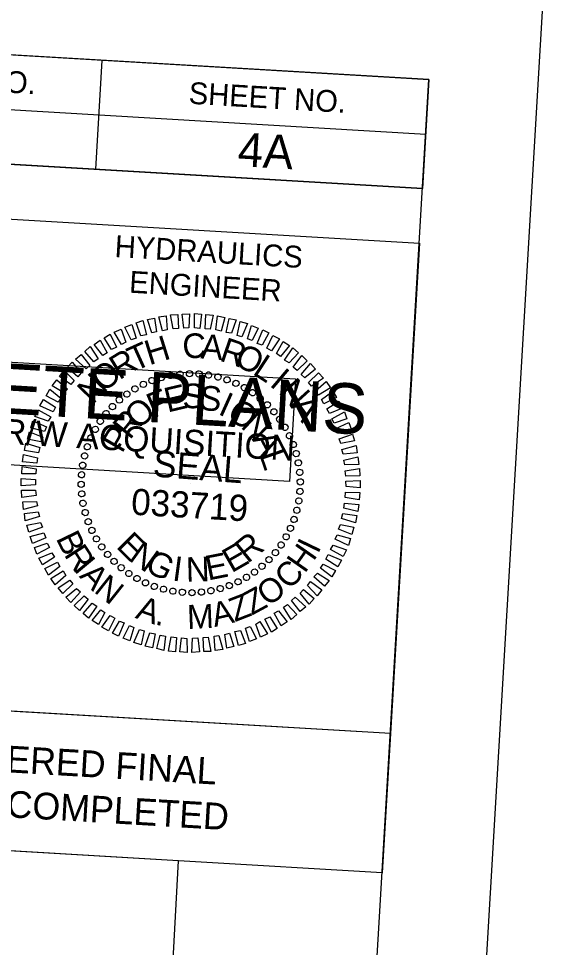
# Model space of a CAD drawing. Extents: x 2010810 to 2012732, y 444258 to 445456.
# Drawn here: x 2012611.9 to 2012732.3, y 445134 to 445346.8 of the extents above; entities that cross this region are included whole.
import ezdxf

# ---------------------------------------------------------------- set-up
doc = ezdxf.new("R2010")
doc.units = 0
for name, color, linetype in [('Sheet Clip Boundary CELL', 7, 'Continuous'), ('Sheet Data Field CELL', 7, 'Continuous'), ('Sheet Plan And Profile CELL', 7, 'Continuous'), ('Sheet Plot Border Outside CELL', 7, 'Continuous'), ('Sheet Professional Seal CELL', 7, 'Continuous'), ('Sheet Profile Grid Minor CELL', 7, 'Continuous'), ('Sheet Sticker Exception Certification CELL', 7, 'Continuous'), ('Sheet Sticker Incomplete CELL', 7, 'Continuous')]:
    doc.layers.add(name, color=color, linetype=linetype)

msp = doc.modelspace()

# ---------------------------------------------------------------- linework, layer by layer
at = {"layer": 'Sheet Clip Boundary CELL'}
msp.add_lwpolyline([(2011147.85, 444375), (2012145.7, 444317.47), (2012151.4, 444414.1), (2011981.99, 444424.08), (2012065.05, 444531.98), (2012116.09, 444528.98), (2012447, 444433.71), (2012447.13, 444434.15), (2012512.37, 444430.3), (2012650.61, 444422.16), (2012668.12, 444720.33), (2012623.18, 444722.98), (2012629.52, 444823.68), (2012643.65, 445063.27), (2012648.58, 445153.9), (2012495.5, 445162.92), (2012502.28, 445278.05), (2012302.58, 445289.82), (2012278.52, 445262.33), (2012176.97, 445268.45), (2011765.99, 445293.2), (2011771.61, 445387.92), (2011477.93, 445405.24)], dxfattribs=at)
at = {"layer": 'Sheet Plan And Profile CELL'}
for p, q in [((2012631.04, 445337.21), (2012629.57, 445312.26)), ((2012505.47, 445332.09), (2012705.17, 445320.32)), ((2012504.73, 445319.61), (2012704.44, 445307.84))]:
    msp.add_line(p, q, dxfattribs=at)
for points in [[(2012705.91, 445332.85), (2011208.51, 445421.12), (2011146.72, 444372.94), (2012644.12, 444284.67)], [(2012506.21, 445344.62), (2012705.91, 445332.85), (2012704.44, 445307.84), (2012504.73, 445319.61)], [(2012603.87, 445301.25), (2012703.7, 445295.36), (2012697.08, 445183.06), (2012597.25, 445188.94)]]:
    msp.add_lwpolyline(points, close=True, dxfattribs=at)
at = {"layer": 'Sheet Plot Border Outside CELL'}
msp.add_lwpolyline([(2010970.55, 444358.28), (2012667.61, 444258.24), (2012732.34, 445356.33), (2011035.28, 445456.37)], close=True, dxfattribs=at)
at = {"layer": 'Sheet Professional Seal CELL'}
for p, q in [((2012646.7, 445265.05), (2012646.7, 445265.05)), ((2012648.92, 445265.32), (2012648.92, 445265.32)), ((2012651.08, 445265.49), (2012651.08, 445265.49)), ((2012653.28, 445265.41), (2012653.28, 445265.41)), ((2012655.47, 445265.13), (2012655.47, 445265.13)), ((2012640.52, 445263.01), (2012640.52, 445263.01)), ((2012642.52, 445263.89), (2012642.52, 445263.89)), ((2012644.56, 445264.57), (2012644.56, 445264.57)), ((2012657.59, 445264.66), (2012657.59, 445264.66)), ((2012659.66, 445264.09), (2012659.66, 445264.09)), ((2012661.72, 445263.26), (2012661.72, 445263.26)), ((2012636.73, 445260.83), (2012636.73, 445260.83)), ((2012638.55, 445261.97), (2012638.55, 445261.97)), ((2012663.66, 445262.25), (2012663.66, 445262.25)), ((2012665.55, 445261.13), (2012665.55, 445261.13)), ((2012634.99, 445259.43), (2012634.99, 445259.43)), ((2012667.27, 445259.78), (2012667.27, 445259.78)), ((2012633.41, 445257.97), (2012633.41, 445257.97)), ((2012668.94, 445258.33), (2012668.94, 445258.33)), ((2012670.4, 445256.74), (2012670.4, 445256.74)), ((2012630.6, 445254.58), (2012630.6, 445254.58)), ((2012631.96, 445256.3), (2012631.96, 445256.3)), ((2012671.8, 445255.01), (2012671.8, 445255.01)), ((2012629.49, 445252.69), (2012629.49, 445252.69)), ((2012672.94, 445253.18), (2012672.94, 445253.18)), ((2012628.47, 445250.75), (2012628.47, 445250.75)), ((2012673.98, 445251.22), (2012673.98, 445251.22)), ((2012627.65, 445248.69), (2012627.65, 445248.69)), ((2012674.86, 445249.22), (2012674.86, 445249.22)), ((2012627.08, 445246.62), (2012627.08, 445246.62)), ((2012675.54, 445247.17), (2012675.54, 445247.17)), ((2012626.6, 445244.5), (2012626.6, 445244.5)), ((2012676.02, 445245.04), (2012676.02, 445245.04)), ((2012626.32, 445242.31), (2012626.32, 445242.31)), ((2012676.29, 445242.82), (2012676.29, 445242.82)), ((2012626.24, 445240.11), (2012626.24, 445240.11)), ((2012651.35, 445240.38), (2012651.35, 445240.38)), ((2012676.46, 445240.66), (2012676.46, 445240.66)), ((2012626.42, 445237.95), (2012626.42, 445237.95)), ((2012676.38, 445238.46), (2012676.38, 445238.46)), ((2012626.69, 445235.73), (2012626.69, 445235.73)), ((2012676.1, 445236.27), (2012676.1, 445236.27)), ((2012627.16, 445233.6), (2012627.16, 445233.6)), ((2012675.63, 445234.14), (2012675.63, 445234.14)), ((2012627.84, 445231.55), (2012627.84, 445231.55)), ((2012675.05, 445232.07), (2012675.05, 445232.07)), ((2012628.73, 445229.55), (2012628.73, 445229.55)), ((2012674.23, 445230.02), (2012674.23, 445230.02)), ((2012629.76, 445227.58), (2012629.76, 445227.58)), ((2012673.22, 445228.08), (2012673.22, 445228.08)), ((2012630.91, 445225.76), (2012630.91, 445225.76)), ((2012670.75, 445224.46), (2012670.75, 445224.46)), ((2012672.1, 445226.19), (2012672.1, 445226.19)), ((2012632.31, 445224.03), (2012632.31, 445224.03)), ((2012633.77, 445222.44), (2012633.77, 445222.44)), ((2012669.3, 445222.8), (2012669.3, 445222.8)), ((2012635.43, 445220.99), (2012635.43, 445220.99)), ((2012667.71, 445221.34), (2012667.71, 445221.34)), ((2012637.16, 445219.63), (2012637.16, 445219.63)), ((2012639.04, 445218.52), (2012639.04, 445218.52)), ((2012664.15, 445218.79), (2012664.15, 445218.79)), ((2012665.97, 445219.94), (2012665.97, 445219.94)), ((2012640.99, 445217.5), (2012640.99, 445217.5)), ((2012643.04, 445216.68), (2012643.04, 445216.68)), ((2012645.11, 445216.11), (2012645.11, 445216.11)), ((2012658.14, 445216.19), (2012658.14, 445216.19)), ((2012660.18, 445216.87), (2012660.18, 445216.87)), ((2012662.19, 445217.76), (2012662.19, 445217.76)), ((2012647.24, 445215.63), (2012647.24, 445215.63)), ((2012649.43, 445215.35), (2012649.43, 445215.35)), ((2012651.63, 445215.27), (2012651.63, 445215.27)), ((2012653.79, 445215.45), (2012653.79, 445215.45)), ((2012656.01, 445215.72), (2012656.01, 445215.72))]:
    msp.add_line(p, q, dxfattribs=at)
for points in [[(2012642.46, 445274.77), (2012641.49, 445277.83), (2012643.06, 445278.19), (2012643.53, 445275.05)], [(2012644.89, 445275.27), (2012644.03, 445278.48), (2012645.75, 445278.73), (2012645.96, 445275.46)], [(2012647.32, 445275.68), (2012646.71, 445278.92), (2012648.37, 445278.98), (2012648.53, 445275.76)], [(2012649.74, 445275.84), (2012649.38, 445279.07), (2012651.08, 445279.17), (2012650.94, 445275.92)], [(2012652.25, 445275.94), (2012652.19, 445279.2), (2012653.83, 445279.05), (2012653.44, 445275.82)], [(2012654.64, 445275.75), (2012654.83, 445279), (2012656.47, 445278.85), (2012655.83, 445275.63)], [(2012657.13, 445275.45), (2012657.52, 445278.69), (2012659.15, 445278.29), (2012658.31, 445275.18)], [(2012659.5, 445274.91), (2012660.14, 445278.08), (2012661.77, 445277.74), (2012660.69, 445274.69)], [(2012635.49, 445272.12), (2012633.8, 445274.93), (2012635.4, 445275.63), (2012636.48, 445272.66)], [(2012637.71, 445273.19), (2012636.28, 445276.08), (2012637.87, 445276.69), (2012638.83, 445273.58)], [(2012639.97, 445274.11), (2012638.84, 445277.08), (2012640.37, 445277.59), (2012641.23, 445274.34)], [(2012662.01, 445274.21), (2012662.7, 445277.43), (2012664.38, 445276.93), (2012663.05, 445273.9)], [(2012664.37, 445273.42), (2012665.3, 445276.48), (2012666.82, 445275.88), (2012665.4, 445273.01)], [(2012633.22, 445271), (2012631.53, 445273.66), (2012632.88, 445274.53), (2012634.36, 445271.54)], [(2012666.56, 445272.39), (2012667.9, 445275.47), (2012669.26, 445274.79), (2012667.69, 445271.98)], [(2012668.75, 445271.31), (2012670.17, 445274.18), (2012671.68, 445273.39), (2012669.82, 445270.7)], [(2012629.15, 445268.19), (2012627.08, 445270.51), (2012628.35, 445271.64), (2012630.14, 445268.83)], [(2012631.24, 445269.62), (2012629.23, 445272.14), (2012630.64, 445273.11), (2012632.22, 445270.21)], [(2012670.98, 445270.03), (2012672.5, 445272.8), (2012673.94, 445271.86), (2012671.89, 445269.37)], [(2012672.85, 445268.57), (2012674.77, 445271.36), (2012676, 445270.23), (2012673.91, 445267.9)], [(2012627.4, 445266.54), (2012624.98, 445268.73), (2012626.29, 445269.81), (2012628.25, 445267.29)], [(2012674.81, 445266.95), (2012676.81, 445269.59), (2012678.05, 445268.41), (2012675.71, 445266.19)], [(2012625.54, 445264.74), (2012623.06, 445266.84), (2012624.24, 445268.08), (2012626.29, 445265.6)], [(2012676.61, 445265.29), (2012678.81, 445267.76), (2012679.94, 445266.5), (2012677.52, 445264.49)], [(2012623.93, 445262.94), (2012621.34, 445264.79), (2012622.37, 445266.18), (2012624.64, 445263.85)], [(2012678.31, 445263.44), (2012680.59, 445265.66), (2012681.72, 445264.39), (2012679.01, 445262.59)], [(2012622.32, 445261.03), (2012619.61, 445262.69), (2012620.69, 445264.03), (2012623.17, 445261.88)], [(2012679.95, 445261.54), (2012682.38, 445263.65), (2012683.34, 445262.24), (2012680.59, 445260.5)], [(2012620.99, 445258.95), (2012618.22, 445260.37), (2012619.06, 445261.87), (2012621.65, 445259.87)], [(2012681.33, 445259.5), (2012683.9, 445261.45), (2012684.76, 445259.95), (2012681.87, 445258.52)], [(2012619.86, 445256.71), (2012616.83, 445258.05), (2012617.67, 445259.55), (2012620.42, 445257.78)], [(2012682.51, 445257.38), (2012685.26, 445259.12), (2012686.12, 445257.57), (2012683.15, 445256.34)], [(2012618.73, 445254.58), (2012615.69, 445255.66), (2012616.43, 445257.17), (2012619.34, 445255.59)], [(2012683.67, 445255.11), (2012686.57, 445256.69), (2012687.13, 445255.1), (2012684.22, 445254.12)], [(2012617.84, 445252.23), (2012614.78, 445253.06), (2012615.23, 445254.68), (2012618.3, 445253.25)], [(2012684.55, 445252.9), (2012687.58, 445254.23), (2012688.13, 445252.59), (2012684.98, 445251.77)], [(2012617.05, 445249.87), (2012613.98, 445250.45), (2012614.43, 445252.13), (2012617.51, 445250.89)], [(2012685.31, 445250.5), (2012688.43, 445251.62), (2012688.89, 445250.04), (2012685.74, 445249.43)], [(2012616.5, 445247.35), (2012613.32, 445247.83), (2012613.62, 445249.52), (2012616.82, 445248.53)], [(2012685.96, 445248.06), (2012689.23, 445249.02), (2012689.43, 445247.35), (2012686.25, 445246.99)], [(2012616.11, 445244.97), (2012612.87, 445245.26), (2012613.07, 445246.9), (2012616.28, 445246.16)], [(2012686.42, 445245.63), (2012689.62, 445246.39), (2012689.82, 445244.68), (2012686.66, 445244.56)], [(2012615.91, 445242.47), (2012612.66, 445242.51), (2012612.76, 445244.21), (2012615.98, 445243.67)], [(2012686.73, 445243.21), (2012690.02, 445243.71), (2012690.07, 445242.01), (2012686.86, 445242)], [(2012615.82, 445239.97), (2012612.55, 445239.77), (2012612.55, 445241.47), (2012615.79, 445241.18)], [(2012686.89, 445240.79), (2012690.16, 445241), (2012690.16, 445239.3), (2012686.92, 445239.59)], [(2012615.97, 445237.56), (2012612.69, 445237.05), (2012612.64, 445238.76), (2012615.85, 445238.77)], [(2012686.79, 445238.29), (2012690.04, 445238.25), (2012689.94, 445236.56), (2012686.72, 445237.1)], [(2012616.28, 445235.14), (2012613.08, 445234.37), (2012612.88, 445236.09), (2012616.05, 445236.2)], [(2012686.59, 445235.8), (2012689.83, 445235.51), (2012689.64, 445233.87), (2012686.42, 445234.61)], [(2012616.74, 445232.71), (2012613.48, 445231.75), (2012613.28, 445233.41), (2012616.45, 445233.78)], [(2012686.2, 445233.42), (2012689.38, 445232.93), (2012689.08, 445231.25), (2012685.88, 445232.24)], [(2012617.4, 445230.26), (2012614.28, 445229.15), (2012613.82, 445230.73), (2012616.96, 445231.34)], [(2012685.65, 445230.9), (2012688.72, 445230.32), (2012688.28, 445228.64), (2012685.19, 445229.87)], [(2012618.16, 445227.86), (2012615.13, 445226.54), (2012614.57, 445228.18), (2012617.72, 445228.99)], [(2012619.03, 445225.66), (2012616.13, 445224.08), (2012615.57, 445225.66), (2012618.49, 445226.64)], [(2012684.86, 445228.54), (2012687.92, 445227.71), (2012687.47, 445226.08), (2012684.4, 445227.52)], [(2012620.2, 445223.39), (2012617.44, 445221.65), (2012616.58, 445223.2), (2012619.56, 445224.43)], [(2012683.97, 445226.19), (2012687.02, 445225.11), (2012686.28, 445223.6), (2012683.36, 445225.17)], [(2012682.85, 445224.05), (2012685.87, 445222.72), (2012685.03, 445221.22), (2012682.28, 445222.98)], [(2012621.38, 445221.26), (2012618.81, 445219.31), (2012617.94, 445220.82), (2012620.83, 445222.25)], [(2012622.76, 445219.23), (2012620.33, 445217.12), (2012619.36, 445218.53), (2012622.12, 445220.27)], [(2012681.71, 445221.81), (2012684.48, 445220.4), (2012683.64, 445218.9), (2012681.06, 445220.9)], [(2012624.4, 445217.33), (2012622.11, 445215.11), (2012620.99, 445216.38), (2012623.7, 445218.17)], [(2012680.39, 445219.74), (2012683.09, 445218.08), (2012682.01, 445216.74), (2012679.54, 445218.89)], [(2012626.09, 445215.48), (2012623.89, 445213), (2012622.77, 445214.27), (2012625.19, 445216.28)], [(2012677.16, 445216.02), (2012679.64, 445213.92), (2012678.47, 445212.69), (2012676.41, 445215.16)], [(2012678.77, 445217.83), (2012681.37, 445215.97), (2012680.33, 445214.58), (2012678.07, 445216.92)], [(2012627.9, 445213.82), (2012625.89, 445211.18), (2012624.66, 445212.36), (2012626.99, 445214.57)], [(2012675.3, 445214.23), (2012677.73, 445212.03), (2012676.41, 445210.96), (2012674.46, 445213.48)], [(2012629.86, 445212.2), (2012627.94, 445209.41), (2012626.7, 445210.53), (2012628.79, 445212.86)], [(2012673.55, 445212.58), (2012675.62, 445210.25), (2012674.35, 445209.13), (2012672.57, 445211.94)], [(2012631.72, 445210.74), (2012630.21, 445207.97), (2012628.76, 445208.91), (2012630.81, 445211.39)], [(2012633.95, 445209.45), (2012632.53, 445206.58), (2012631.02, 445207.37), (2012632.89, 445210.07)], [(2012669.48, 445209.76), (2012671.18, 445207.11), (2012669.82, 445206.24), (2012668.35, 445209.23)], [(2012671.47, 445211.15), (2012673.47, 445208.63), (2012672.06, 445207.66), (2012670.48, 445210.56)], [(2012636.14, 445208.37), (2012634.81, 445205.3), (2012633.45, 445205.98), (2012635.01, 445208.79)], [(2012638.34, 445207.34), (2012637.4, 445204.29), (2012635.89, 445204.88), (2012637.31, 445207.75)], [(2012665, 445207.57), (2012666.43, 445204.68), (2012664.84, 445204.08), (2012663.87, 445207.19)], [(2012667.21, 445208.65), (2012668.9, 445205.84), (2012667.31, 445205.13), (2012666.23, 445208.1)], [(2012640.69, 445206.55), (2012640, 445203.34), (2012638.33, 445203.84), (2012639.66, 445206.86)], [(2012643.21, 445205.85), (2012642.57, 445202.68), (2012640.94, 445203.03), (2012642.02, 445206.07)], [(2012645.58, 445205.31), (2012645.19, 445202.08), (2012643.56, 445202.48), (2012644.39, 445205.58)], [(2012657.81, 445205.49), (2012658.67, 445202.29), (2012656.96, 445202.04), (2012656.75, 445205.31)], [(2012660.24, 445206), (2012661.22, 445202.94), (2012659.64, 445202.58), (2012659.18, 445205.71)], [(2012662.74, 445206.65), (2012663.86, 445203.68), (2012662.33, 445203.17), (2012661.47, 445206.43)], [(2012648.07, 445205.02), (2012647.87, 445201.77), (2012646.23, 445201.92), (2012646.87, 445205.14)], [(2012650.46, 445204.82), (2012650.52, 445201.57), (2012648.87, 445201.71), (2012649.26, 445204.94)], [(2012652.97, 445204.93), (2012653.33, 445201.7), (2012651.62, 445201.6), (2012651.76, 445204.85)], [(2012655.38, 445205.09), (2012655.99, 445201.84), (2012654.34, 445201.79), (2012654.18, 445205.01)]]:
    msp.add_lwpolyline(points, close=True, dxfattribs=at)
for centre, major_axis in [((2012644.6, 445264.54), (-0.194, 0.693)), ((2012646.73, 445265.03), (-0.133, 0.708)), ((2012648.89, 445265.34), (-0.071, 0.717)), ((2012651.08, 445265.46), (-0.008, 0.72)), ((2012653.26, 445265.39), (0.055, 0.718)), ((2012655.44, 445265.13), (0.117, 0.71)), ((2012657.58, 445264.68), (0.179, 0.697)), ((2012659.67, 445264.04), (0.239, 0.679)), ((2012638.58, 445261.96), (-0.367, 0.62)), ((2012640.51, 445263), (-0.311, 0.649)), ((2012642.52, 445263.86), (-0.254, 0.674)), ((2012661.7, 445263.23), (0.297, 0.656)), ((2012663.65, 445262.24), (0.353, 0.627)), ((2012636.74, 445260.77), (-0.419, 0.585)), ((2012665.51, 445261.08), (0.407, 0.594)), ((2012633.43, 445257.92), (-0.515, 0.504)), ((2012635.02, 445259.42), (-0.469, 0.546)), ((2012667.26, 445259.77), (0.457, 0.557)), ((2012668.89, 445258.31), (0.504, 0.515)), ((2012631.96, 445256.29), (-0.557, 0.457)), ((2012670.39, 445256.71), (0.546, 0.469)), ((2012630.65, 445254.54), (-0.594, 0.407)), ((2012671.74, 445254.99), (0.585, 0.419)), ((2012629.5, 445252.69), (-0.627, 0.353)), ((2012672.93, 445253.16), (0.62, 0.367)), ((2012628.51, 445250.73), (-0.656, 0.297)), ((2012673.97, 445251.23), (0.649, 0.311)), ((2012674.82, 445249.22), (0.674, 0.254)), ((2012627.69, 445248.7), (-0.679, 0.239)), ((2012675.51, 445247.14), (0.693, 0.194)), ((2012627.06, 445246.61), (-0.697, 0.179)), ((2012676, 445245.01), (0.708, 0.133)), ((2012626.61, 445244.47), (-0.71, 0.117)), ((2012676.31, 445242.84), (0.717, 0.071)), ((2012626.35, 445242.3), (-0.718, 0.055)), ((2012626.27, 445240.11), (-0.72, -0.008)), ((2012676.43, 445240.66), (0.72, 0.008)), ((2012626.39, 445237.92), (-0.717, -0.071)), ((2012676.36, 445238.47), (0.718, -0.055)), ((2012626.7, 445235.76), (-0.708, -0.133)), ((2012676.1, 445236.3), (0.71, -0.117)), ((2012627.2, 445233.63), (-0.693, -0.194)), ((2012675.65, 445234.16), (0.697, -0.179)), ((2012627.88, 445231.55), (-0.674, -0.254)), ((2012674.2, 445230.03), (0.656, -0.297)), ((2012675.01, 445232.06), (0.679, -0.239)), ((2012628.74, 445229.54), (-0.649, -0.311)), ((2012673.21, 445228.08), (0.627, -0.353)), ((2012629.77, 445227.61), (-0.62, -0.367)), ((2012630.97, 445225.77), (-0.585, -0.419)), ((2012672.05, 445226.22), (0.594, -0.407)), ((2012632.32, 445224.05), (-0.546, -0.469)), ((2012670.74, 445224.47), (0.557, -0.457)), ((2012633.81, 445222.46), (-0.504, -0.515)), ((2012669.28, 445222.84), (0.515, -0.504)), ((2012635.44, 445221), (-0.457, -0.557)), ((2012637.19, 445219.68), (-0.407, -0.594)), ((2012665.96, 445220), (0.419, -0.585)), ((2012667.68, 445221.35), (0.469, -0.546)), ((2012639.05, 445218.53), (-0.353, -0.627)), ((2012641, 445217.54), (-0.297, -0.656)), ((2012662.2, 445217.77), (0.311, -0.649)), ((2012664.13, 445218.8), (0.367, -0.62)), ((2012643.03, 445216.72), (-0.239, -0.679)), ((2012645.13, 445216.09), (-0.179, -0.697)), ((2012647.27, 445215.64), (-0.117, -0.71)), ((2012649.44, 445215.38), (-0.055, -0.718)), ((2012651.63, 445215.3), (0.008, -0.72)), ((2012653.81, 445215.42), (0.071, -0.717)), ((2012655.98, 445215.73), (0.133, -0.708)), ((2012658.11, 445216.23), (0.194, -0.693)), ((2012660.19, 445216.91), (0.254, -0.674))]:
    msp.add_ellipse(centre, major_axis=major_axis, ratio=0.999708, dxfattribs=at)
at = {"layer": 'Sheet Sticker Exception Certification CELL'}
for p, q in [((2012497.38, 445194.85), (2012697.08, 445183.08)), ((2012697.08, 445183.06), (2012695.2, 445151.13)), ((2012695.2, 445151.15), (2012495.5, 445162.92))]:
    msp.add_line(p, q, dxfattribs=at)
at = {"layer": 'Sheet Sticker Incomplete CELL'}
msp.add_lwpolyline([(2012527.19, 445249.42), (2012528.57, 445272.88), (2012675.32, 445264.23), (2012673.94, 445240.77)], close=True, dxfattribs=at)

# ---------------------------------------------------------------- texts
at = {"layer": 'Sheet Data Field CELL'}
msp.add_text('4A', height=7.75, rotation=356.6264, dxfattribs=at).set_placement((2012661.98, 445313))
at = {"layer": 'Sheet Plan And Profile CELL'}
for s, height, p in [('PROJECT REFERENCE NO.', 5.0001, (2012527.86, 445334.63)), ('SHEET NO.', 5, (2012650.79, 445327.28)), ('HYDRAULICS', 5, (2012633.84, 445292.17)), ('ENGINEER', 5, (2012637.17, 445284.01))]:
    msp.add_text(s, height=height, rotation=356.6264, dxfattribs=at).set_placement(p)
at = {"layer": 'Sheet Professional Seal CELL'}
for s, height, rotation, p in [('H', 5.64, 17.2459, (2012641.87, 445267.34)), ('C', 5.64, 2.8463, (2012649.58, 445268.89)), ('A', 5.64, 355.6467, (2012653.54, 445268.95)), ('R', 5.64, 341.2475, (2012657.72, 445268.51)), ('T', 5.64, 24.4462, (2012638.53, 445265.88)), ('O', 5.64, 334.0476, (2012661.02, 445267.56)), ('R', 5.64, 31.6469, (2012635.01, 445263.89)), ('L', 5.64, 326.8473, (2012665.3, 445265.46)), ('O', 5.64, 38.8482, (2012631.38, 445260.99)), ('N', 5.64, 46.0499, (2012628.91, 445258.23)), ('I', 5.64, 319.6466, (2012669.2, 445262.82)), ('E', 5.64, 13.2375, (2012646.04, 445256.52)), ('S', 5.64, 3.882, (2012649.55, 445257.37)), ('S', 5.64, 354.5268, (2012653.15, 445257.21)), ('N', 5.64, 312.4453, (2012671.26, 445261.15)), ('F', 5.64, 22.5935, (2012642.76, 445255.21)), ('I', 5.64, 335.816, (2012657.4, 445256.26)), ('O', 5.64, 41.3077, (2012639.29, 445252.46)), ('O', 5.64, 326.4599, (2012659.35, 445255.44)), ('A', 5.64, 305.2436, (2012674.03, 445258.03)), ('R', 5.64, 50.6661, (2012637.4, 445250.12)), ('N', 5.64, 317.103, (2012662.58, 445253.24)), ('P', 5.64, 60.0253, (2012635.62, 445247.02)), ('A', 5.64, 298.3867, (2012665.27, 445250.48)), ('SEAL', 5.998, 355.6264, (2012642.58, 445241.9)), ('L', 5.64, 289.0273, (2012667.01, 445246.92)), ('E', 5.64, 314.9033, (2012634.06, 445225.73)), ('R', 5.64, 39.1078, (2012664.38, 445221.83)), ('N', 5.64, 324.2604, (2012636.9, 445222.85)), ('E', 5.64, 29.7505, (2012660.7, 445219.7)), ('G', 5.64, 333.6167, (2012640.56, 445220.38)), ('E', 5.64, 11.0382, (2012655.3, 445218.06)), ('I', 5.64, 352.3276, (2012646.98, 445218.1)), ('N', 5.64, 1.6828, (2012650.32, 445217.75))]:
    msp.add_text(s, height=height, rotation=rotation, dxfattribs=at).set_placement(p)
at = {"layer": 'Sheet Profile Grid Minor CELL'}
for s, height, rotation, p in [('033719', 5.998, 356.6264, (2012637.59, 445233.17)), ('B', 5.5, 295.7793, (2012620.41, 445227.74)), ('H', 5.5, 54.9743, (2012677.48, 445219.54)), ('I', 5.5, 64.2191, (2012680.49, 445224)), ('R', 5.5, 302.9061, (2012622.21, 445224)), ('I', 5.5, 309.8326, (2012624.4, 445220.61)), ('C', 5.5, 46.1015, (2012673.95, 445215.75)), ('A', 5.5, 313.353, (2012625.67, 445218.99)), ('N', 5.5, 321.5388, (2012628.98, 445215.55)), ('O', 5.5, 35.397, (2012668.99, 445211.98)), ('Z', 5.5, 28.2703, (2012665.33, 445210.02)), ('A', 5.5, 340.9157, (2012638.48, 445209.53)), ('Z', 5.5, 21.1435, (2012661.45, 445208.52)), ('M', 5.5, 2.2818, (2012650.61, 445206.96)), ('A', 5.5, 12.9577, (2012656.81, 445207.4)), ('.', 5.5, 349.1015, (2012643.01, 445208.01))]:
    msp.add_text(s, height=height, rotation=rotation, dxfattribs=at).set_placement(p)
at = {"layer": 'Sheet Sticker Exception Certification CELL'}
for s, p in [('DOCUMENT NOT CONSIDERED FINAL', (2012508.16, 445180.11)), ('UNLESS ALL SIGNATURES COMPLETED', (2012501.83, 445170.2))]:
    msp.add_text(s, height=6.124, rotation=356.6264, dxfattribs=at).set_placement(p)
at = {"layer": 'Sheet Sticker Incomplete CELL'}
for s, height, p in [('INCOMPLETE PLANS', 11.52, (2012536.81, 445260.57)), ('DO NOT USE FOR R/W ACQUISITION', 5.76, (2012539.65, 445253.45))]:
    msp.add_text(s, height=height, rotation=356.6264, dxfattribs=at).set_placement(p)

doc.saveas('drawing.dxf')
